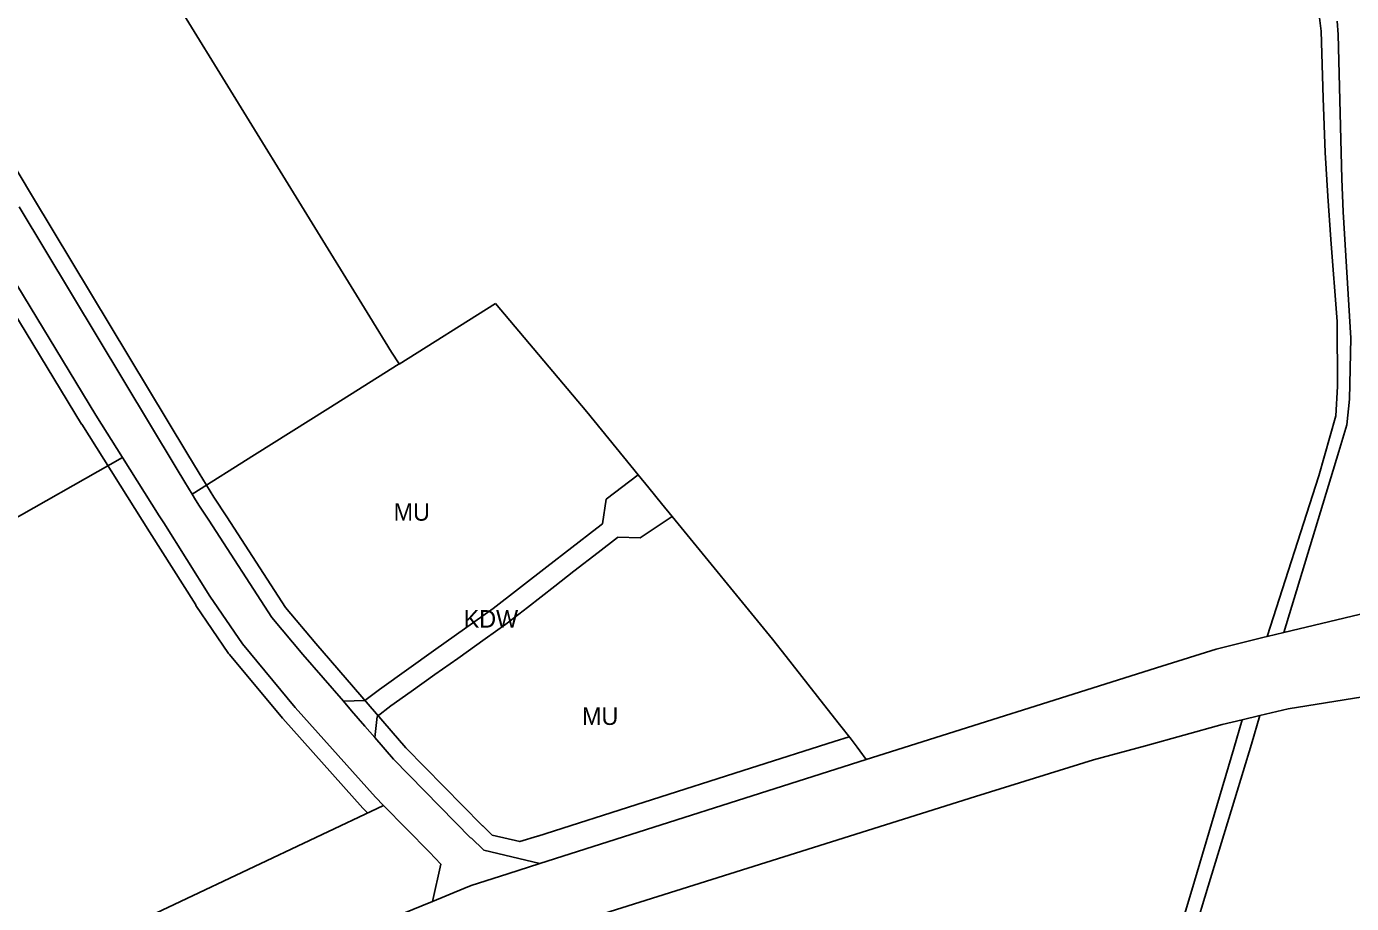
# Model space of a CAD drawing. Extents: x 7435758 to 7439981, y 5550649 to 5554049.
# Drawn here: x 7437843.8 to 7438238.4, y 5551083.7 to 5551344.8 of the extents above; entities that cross this region are included whole.
import ezdxf

# ---------------------------------------------------------------- set-up
doc = ezdxf.new("R2010")
doc.units = 0
for name, color, linetype in [('linie_rozgraniczające', 7, 'Continuous'), ('linie_zabudowy_nieprzekraczalne', 7, 'Continuous'), ('oznaczenia_przeznaczen', 7, 'Continuous')]:
    doc.layers.add(name, color=color, linetype=linetype)

msp = doc.modelspace()

# ---------------------------------------------------------------- linework, layer by layer
at = {"layer": 'linie_rozgraniczające'}
for p, q in [((7437946.07, 5551258.39), (7437844.14, 5551423.82)), ((7438228.92, 5551347.4), (7438229.34, 5551343.38)), ((7438234.42, 5551342.4), (7438234.12, 5551346.36)), ((7438229.34, 5551343.38), (7438230.01, 5551323.5)), ((7438235.52, 5551299.41), (7438234.42, 5551342.4)), ((7438230.01, 5551323.5), (7438230.54, 5551307.29)), ((7438230.54, 5551307.29), (7438231.39, 5551294.31)), ((7438235.91, 5551289.65), (7438235.52, 5551299.41)), ((7438231.39, 5551294.31), (7438232.2, 5551281.4)), ((7437888.41, 5551213.45), (7437841.65, 5551291.1)), ((7437829.46, 5551286.7), (7437864.51, 5551229.05)), ((7438238.22, 5551252.07), (7438235.91, 5551289.65)), ((7438232.2, 5551281.4), (7438234.12, 5551256.95)), ((7437983.5, 5551262.32), (7437954.77, 5551244.32)), ((7438010.66, 5551230.1), (7437983.5, 5551262.32)), ((7437952.55, 5551247.88), (7437946.07, 5551258.39)), ((7438234.12, 5551256.95), (7438234.19, 5551237.61)), ((7438237.85, 5551233.84), (7438238.22, 5551252.07)), ((7437952.56, 5551247.89), (7437952.55, 5551247.88)), ((7437954.75, 5551244.35), (7437952.56, 5551247.89)), ((7437954.75, 5551244.35), (7437933.6, 5551231)), ((7437954.77, 5551244.32), (7437954.75, 5551244.35)), ((7438234.19, 5551237.61), (7438233.69, 5551228.91)), ((7437933.6, 5551231), (7437911.72, 5551217.25)), ((7438237.04, 5551226.25), (7438237.85, 5551233.84)), ((7437864.51, 5551229.05), (7437872.41, 5551216.5)), ((7438025.96, 5551211.38), (7438010.66, 5551230.1)), ((7438233.69, 5551228.91), (7438228.66, 5551211)), ((7438234.59, 5551218.26), (7438237.04, 5551226.25)), ((7437763.36, 5551154.58), (7437872.41, 5551216.5)), ((7437872.41, 5551216.5), (7437883.32, 5551199.18)), ((7437911.72, 5551217.25), (7437893.13, 5551205.62)), ((7438218.29, 5551164.39), (7438234.59, 5551218.26)), ((7437890.99, 5551209.18), (7437888.41, 5551213.45)), ((7438016.43, 5551204.1), (7438025.96, 5551211.38)), ((7438029.13, 5551207.51), (7438025.96, 5551211.38)), ((7437893.13, 5551205.62), (7437890.99, 5551209.18)), ((7438032.94, 5551202.85), (7438029.13, 5551207.51)), ((7438228.66, 5551211), (7438213.32, 5551163.2)), ((7437894.17, 5551203.89), (7437893.13, 5551205.62)), ((7437895.37, 5551202.05), (7437894.17, 5551203.89)), ((7438015.36, 5551196.79), (7438016.43, 5551204.1)), ((7437898.09, 5551197.85), (7437895.37, 5551202.05)), ((7438036.1, 5551198.97), (7438032.94, 5551202.85)), ((7437883.32, 5551199.18), (7437884.69, 5551197)), ((7437884.69, 5551197), (7437898.43, 5551175.26)), ((7437916.91, 5551168.85), (7437898.09, 5551197.85)), ((7437998.81, 5551183.96), (7438013.64, 5551195.45)), ((7438013.64, 5551195.45), (7438015.36, 5551196.79)), ((7438036.1, 5551198.97), (7438026.54, 5551192.57)), ((7438065.99, 5551162.41), (7438036.1, 5551198.97)), ((7438019.83, 5551192.69), (7438014.01, 5551188.19)), ((7438019.9, 5551192.75), (7438019.83, 5551192.69)), ((7438026.54, 5551192.57), (7438019.9, 5551192.75)), ((7438014.01, 5551188.19), (7438006.86, 5551182.64)), ((7437982.77, 5551171.57), (7437998.81, 5551183.96)), ((7438006.86, 5551182.64), (7438001.13, 5551178.17)), ((7438001.13, 5551178.17), (7437992.97, 5551171.88)), ((7437898.43, 5551175.26), (7437908.12, 5551161.01)), ((7437992.97, 5551171.88), (7437986.52, 5551166.85)), ((7437926.15, 5551157.83), (7437916.91, 5551168.85)), ((7437965.7, 5551159.4), (7437982.77, 5551171.57)), ((7438245.26, 5551170.82), (7438218.29, 5551164.39)), ((7437986.52, 5551166.85), (7437980.36, 5551162.48)), ((7438213.32, 5551163.2), (7438218.29, 5551164.39)), ((7437908.12, 5551161.01), (7437923.85, 5551142.12)), ((7437980.36, 5551162.48), (7437972.23, 5551156.71)), ((7438070.02, 5551157.28), (7438065.99, 5551162.41)), ((7438212.44, 5551163), (7438198.14, 5551159.49)), ((7438213.32, 5551163.2), (7438212.44, 5551163)), ((7437938.19, 5551143.93), (7437926.15, 5551157.83)), ((7437948.93, 5551147.48), (7437965.7, 5551159.4)), ((7437972.23, 5551156.71), (7437965.45, 5551151.88)), ((7438081.17, 5551143.11), (7438070.02, 5551157.28)), ((7438198.14, 5551159.49), (7438181.91, 5551154.38)), ((7438181.9, 5551154.38), (7438093.82, 5551126.63)), ((7438181.91, 5551154.38), (7438181.9, 5551154.38)), ((7437965.45, 5551151.88), (7437958.37, 5551146.82)), ((7438219.56, 5551141.68), (7438278.56, 5551151.11)), ((7437938.19, 5551143.93), (7437944.61, 5551144.15)), ((7437944.61, 5551144.15), (7437948.93, 5551147.48)), ((7437958.37, 5551146.82), (7437952.32, 5551142.54)), ((7437923.85, 5551142.12), (7437947.72, 5551115.42)), ((7437940.64, 5551141.1), (7437938.19, 5551143.93)), ((7437944.59, 5551136.55), (7437940.64, 5551141.1)), ((7437952.32, 5551142.54), (7437948.22, 5551139.42)), ((7438085.94, 5551137.04), (7438081.17, 5551143.11)), ((7438211.12, 5551139.67), (7438219.56, 5551141.68)), ((7437947.51, 5551133.18), (7437944.59, 5551136.55)), ((7437948.22, 5551139.42), (7437947.51, 5551133.18)), ((7438089.38, 5551132.68), (7438085.94, 5551137.04)), ((7438177.08, 5551130.68), (7438199.86, 5551136.99)), ((7438199.86, 5551136.99), (7438205.88, 5551138.43)), ((7438205.88, 5551138.43), (7438203.32, 5551129.9)), ((7438211.12, 5551139.67), (7438205.88, 5551138.43)), ((7438208.65, 5551131.19), (7438211.12, 5551139.67)), ((7437953.12, 5551126.71), (7437947.51, 5551133.18)), ((7438091.16, 5551130.25), (7438089.38, 5551132.68)), ((7438091.96, 5551129.16), (7438091.16, 5551130.25)), ((7438093.82, 5551126.63), (7438091.96, 5551129.16)), ((7438161.55, 5551126.47), (7438177.08, 5551130.68)), ((7438203.32, 5551129.9), (7438191.67, 5551090.4)), ((7438203.64, 5551114.88), (7438208.65, 5551131.19)), ((7437976.17, 5551103.22), (7437953.12, 5551126.71)), ((7438093.82, 5551126.63), (7437996.66, 5551095.64)), ((7438126.39, 5551115.61), (7438161.55, 5551126.47)), ((7437950.17, 5551112.94), (7437826.06, 5551054.35)), ((7437947.72, 5551115.42), (7437950.17, 5551112.94)), ((7437950.17, 5551112.94), (7437963.83, 5551099.06)), ((7438015.73, 5551080.78), (7438126.39, 5551115.61)), ((7438195.69, 5551088.86), (7438203.64, 5551114.88)), ((7437976.2, 5551103.23), (7437976.17, 5551103.22)), ((7437979.96, 5551099.57), (7437976.2, 5551103.23)), ((7437963.83, 5551099.06), (7437963.78, 5551099.05)), ((7437963.78, 5551099.05), (7437963.81, 5551099.05)), ((7437963.81, 5551099.05), (7437967.18, 5551095.47)), ((7437996.66, 5551095.64), (7437979.96, 5551099.57)), ((7437967.18, 5551095.47), (7437964.76, 5551084.36)), ((7437987.14, 5551092.57), (7437996.66, 5551095.64)), ((7437974.07, 5551088.17), (7437976.25, 5551089.06)), ((7437976.25, 5551089.06), (7437987.14, 5551092.57)), ((7438191.67, 5551090.4), (7438183.97, 5551065.05)), ((7438187.24, 5551061.22), (7438195.69, 5551088.86)), ((7437964.76, 5551084.36), (7437974.07, 5551088.17)), ((7437949.85, 5551078.26), (7437964.76, 5551084.36))]:
    msp.add_line(p, q, dxfattribs=at)
at = {"layer": 'linie_zabudowy_nieprzekraczalne'}
for points in [[(7437945.38, 5551110.68), (7437944.16, 5551111.91), (7437944.1, 5551111.98), (7437943.99, 5551112.09), (7437920.13, 5551138.79), (7437920.01, 5551138.92), (7437904.28, 5551157.81), (7437904.08, 5551158.06), (7437903.98, 5551158.2), (7437894.29, 5551172.45), (7437894.2, 5551172.59), (7437880.46, 5551194.33), (7437880.46, 5551194.33), (7437860.28, 5551226.39), (7437860.24, 5551226.45), (7437825.19, 5551284.1), (7437825.13, 5551284.2), (7437785.07, 5551353.65), (7437753.35, 5551406.01), (7437753.34, 5551406.04), (7437746.65, 5551417.27), (7437742.73, 5551423.43)], [(7437793.4, 5551381.52), (7437845.93, 5551293.68), (7437891.6, 5551217.86), (7437895.22, 5551211.84), (7437899.6, 5551204.71), (7437903.43, 5551198.8), (7437920.94, 5551171.83), (7437929.95, 5551161.08), (7437956.8, 5551130.1), (7437979.4, 5551107.07), (7437979.59, 5551106.9), (7437979.69, 5551106.81), (7437982.45, 5551104.12), (7437990.7, 5551102.18), (7437996.04, 5551103.81), (7437996.06, 5551103.82), (7438059.45, 5551124), (7438084.33, 5551131.93), (7438088.83, 5551133.36)]]:
    msp.add_lwpolyline(points, dxfattribs=at)

# ---------------------------------------------------------------- texts
at = {"layer": 'oznaczenia_przeznaczen'}
for s, p in [('MU', (7437953.14, 5551197.69)), ('KDW', (7437974, 5551165.87)), ('MU', (7438009.25, 5551136.89))]:
    msp.add_text(s, height=5.2, dxfattribs=at).set_placement(p)

doc.saveas('drawing.dxf')
